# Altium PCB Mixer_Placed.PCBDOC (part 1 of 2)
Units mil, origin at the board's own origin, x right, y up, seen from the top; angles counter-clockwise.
Board outline 16350 x 11350 mil, 2 copper layers (TopLayer, BottomLayer); 554 components, 386 nets, 1551 pads, 0 vias.
Unrouted connection lines stored in the file: 1047.
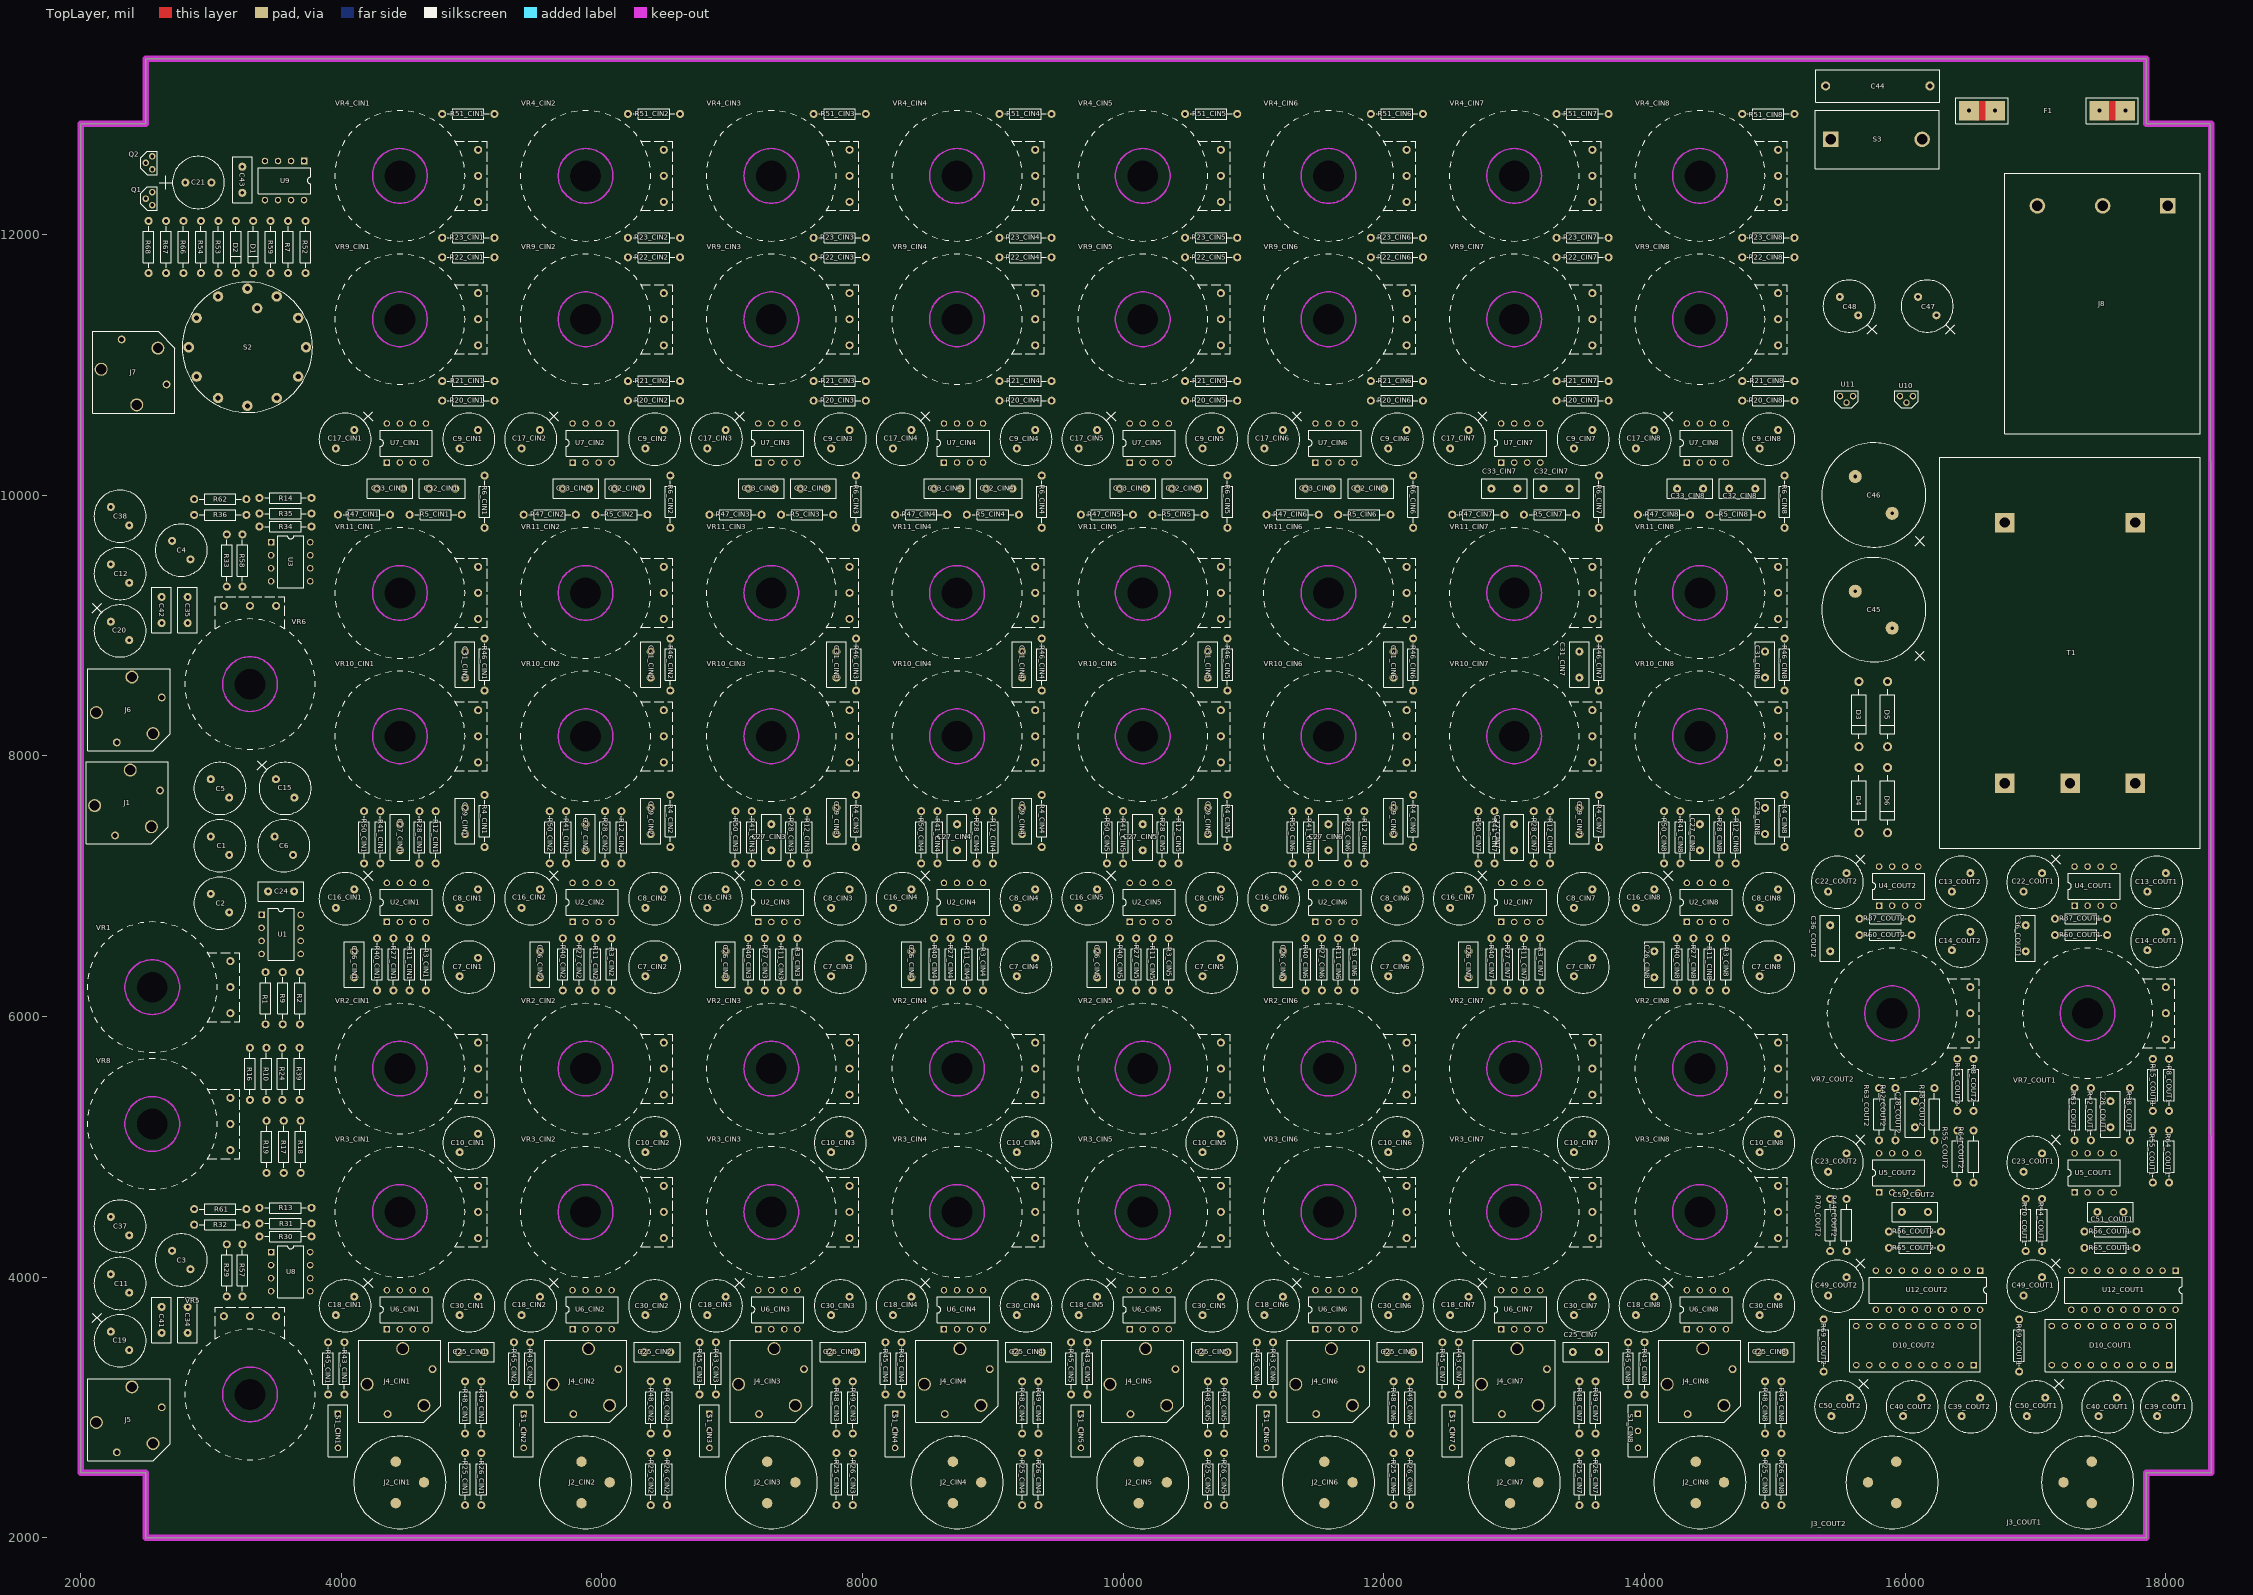
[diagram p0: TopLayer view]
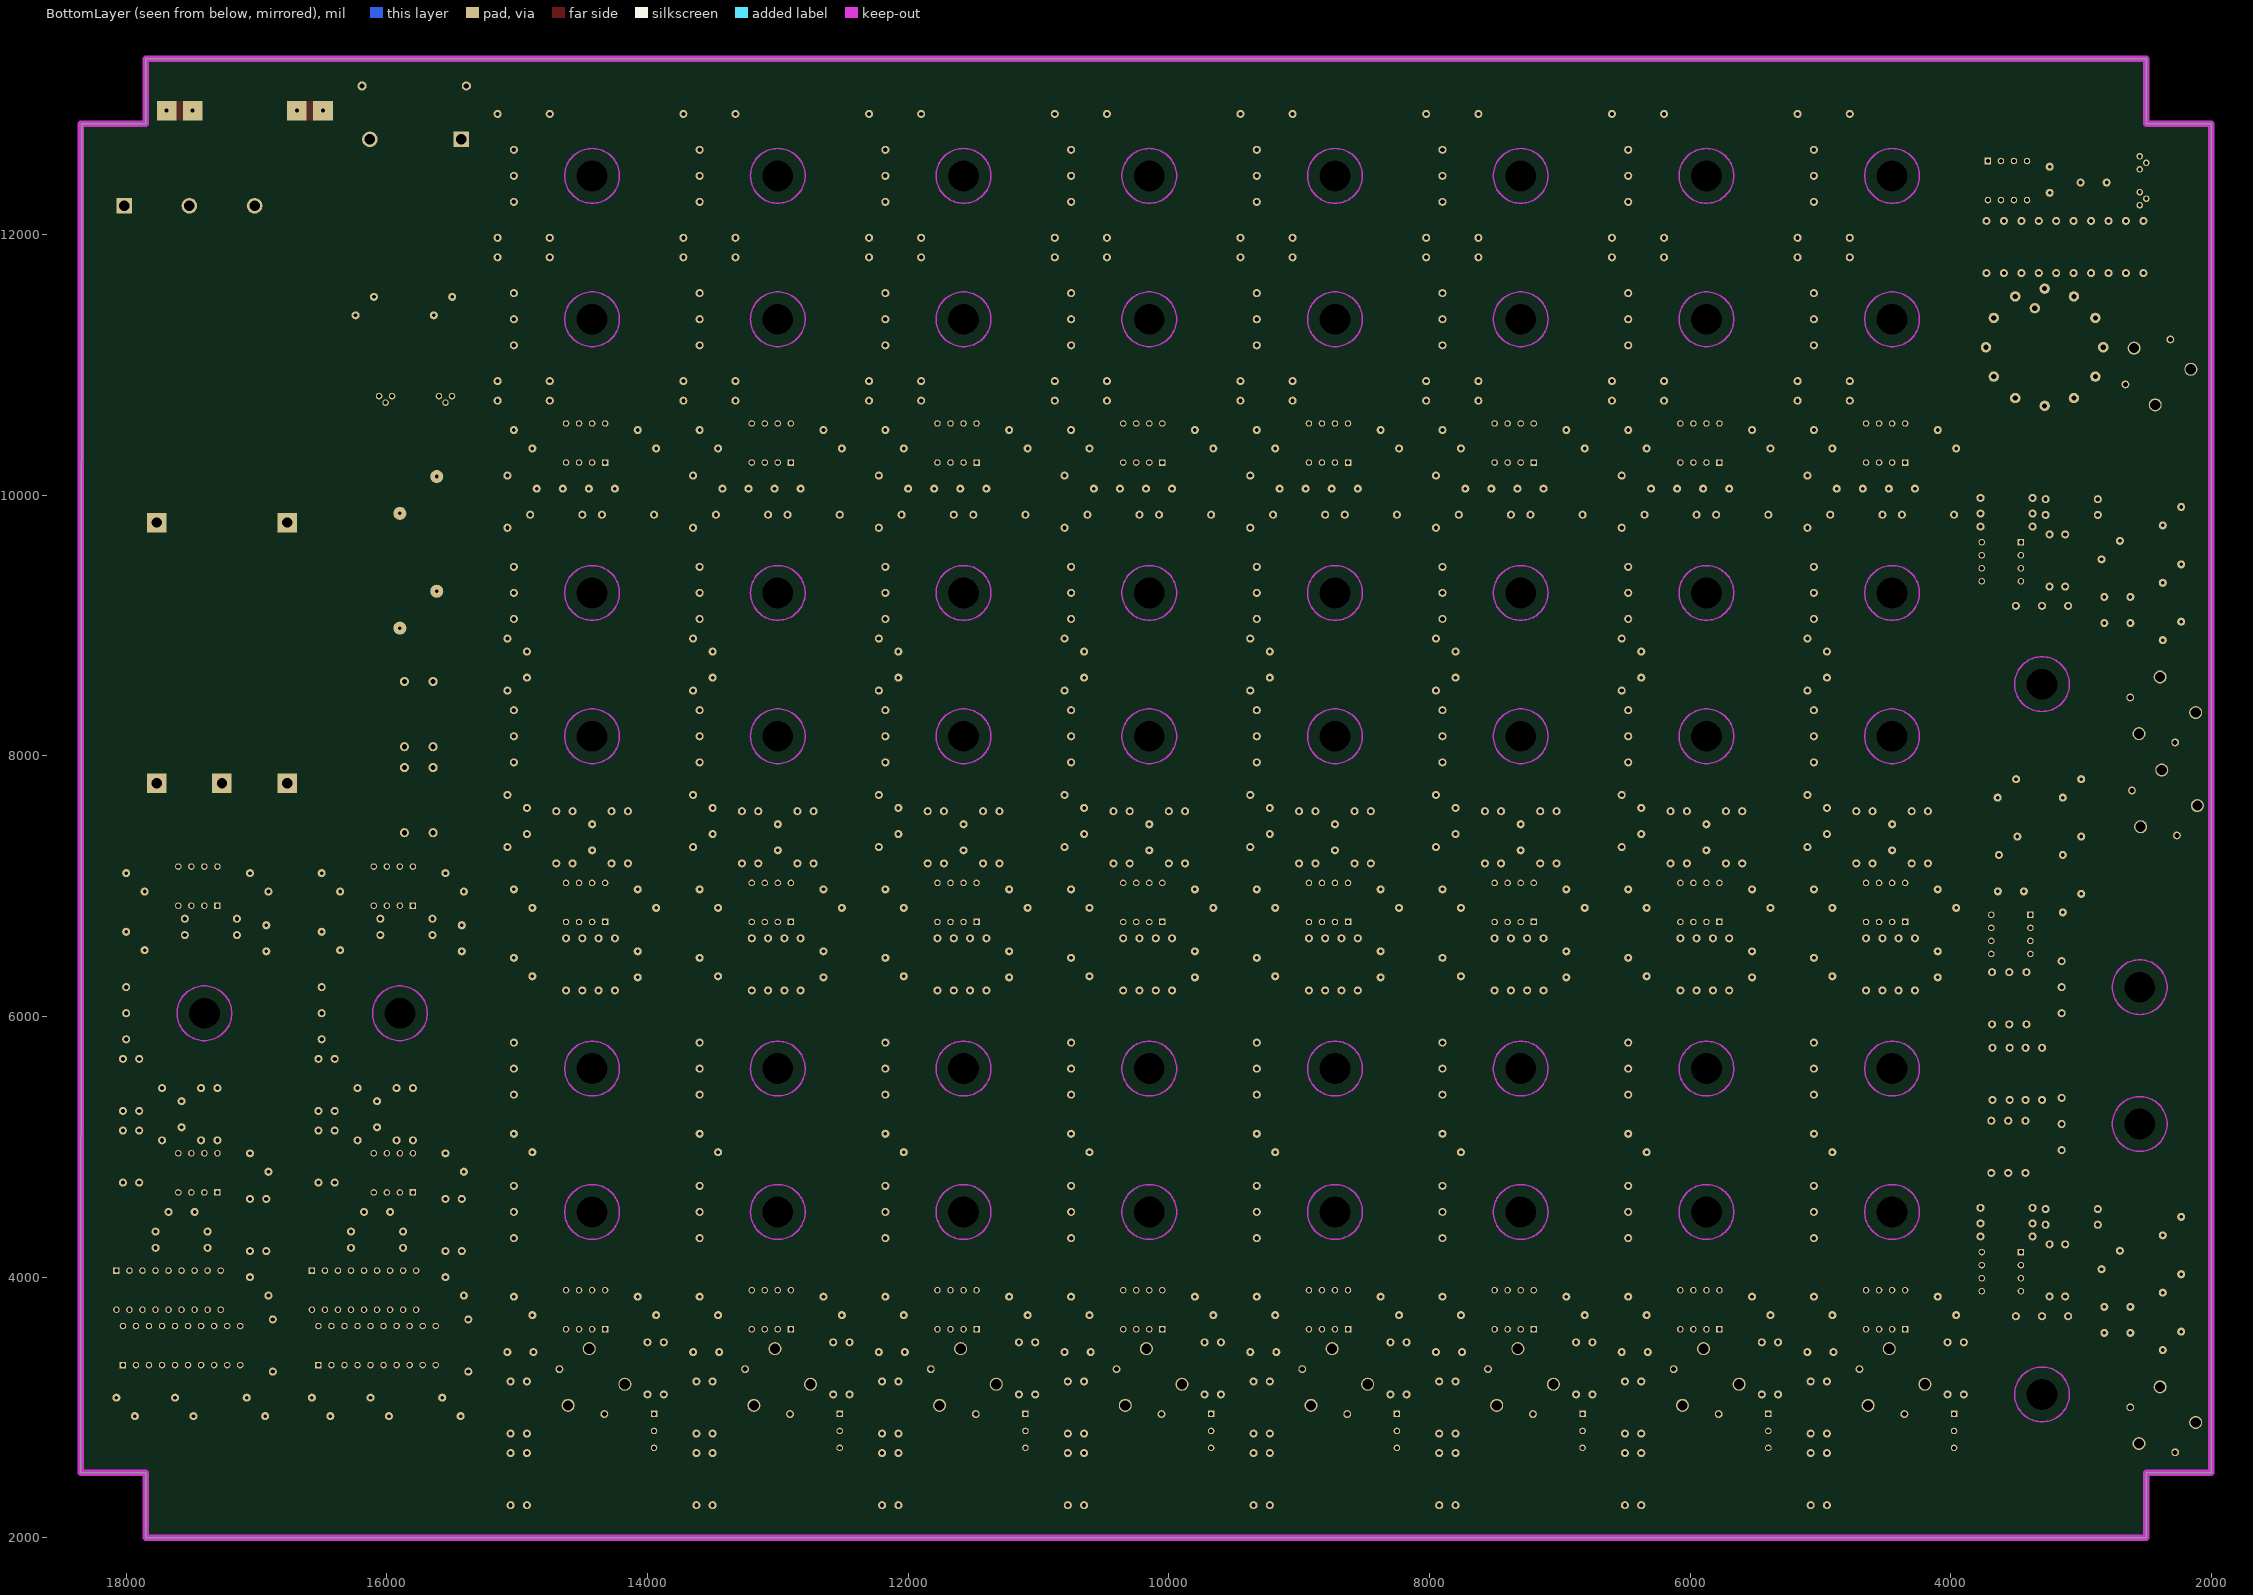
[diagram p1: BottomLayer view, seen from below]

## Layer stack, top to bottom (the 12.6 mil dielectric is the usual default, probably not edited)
TopLayer: signal copper 1.4
Dielectric: core 12.6, FR-4, Dk 4.8
BottomLayer: signal copper 1.4

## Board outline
17850,2500 18350,2500 18340,12850 17850,12850 17850,13350 2500,13350 2500,12850 2000,12850 2000,2500 2500,2500 2500,2000 17850,2000 17850,2500

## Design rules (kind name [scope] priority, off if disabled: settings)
Clearance Clearance_Mains [InNetClass('Mains Voltages') vs Not OnLayer(KeepOutLayer)] p1: gap=100
Clearance [All] p2: gap=10
FabricationTestPointUsage TestPointUsage [All] p1: valid=0 allowmultiple=FALSE
FabricationTestpoint Testpoint [All] p1: side=3 testpointundercomponent=TRUE minsize=40 maxsize=100 preferedsize=60 minholesize=20 maxholesize=40 preferedholesize=32 testpointgrid=1 allowsidetop=TRUE allowsidebottom=TRUE usegrid=TRUE gridtolerance=0.01
PlaneClearance [All] p1: clearance=10
PolygonConnect [All] p1: connectstyle=Relief reliefconductorwidth=10 reliefentries=4 polygonreliefangle="90 Angle"
RoomDefinition CIN7 [InComponentClass('CIN7') vs False] p1: confinementstyle=ConfineIn formatcopy=TRUE lockcomponents=FALSE outline 12350,2050 13775,2050 13775,13300 12350,13300
RoomDefinition CIN6 [InComponentClass('CIN6') vs False] p2: confinementstyle=ConfineIn formatcopy=TRUE lockcomponents=FALSE outline 10925,2050 12350,2050 12350,13300 10925,13300
RoomDefinition CIN5 [InComponentClass('CIN5') vs False] p3: confinementstyle=ConfineIn formatcopy=TRUE lockcomponents=FALSE outline 9500,2050 10925,2050 10925,13300 9500,13300
RoomDefinition CIN4 [InComponentClass('CIN4') vs False] p4: confinementstyle=ConfineIn formatcopy=TRUE lockcomponents=FALSE outline 8075,2050 9500,2050 9500,13300 8075,13300
RoomDefinition CIN3 [InComponentClass('CIN3') vs False] p5: confinementstyle=ConfineIn formatcopy=TRUE lockcomponents=FALSE outline 6650,2050 8075,2050 8075,13300 6650,13300
RoomDefinition CIN2 [InComponentClass('CIN2') vs False] p6: confinementstyle=ConfineIn formatcopy=TRUE lockcomponents=FALSE outline 5225,2050 6650,2050 6650,13300 5225,13300
RoomDefinition CIN1 [InComponentClass('CIN1') vs False] p7: confinementstyle=ConfineIn formatcopy=TRUE lockcomponents=FALSE outline 3800,2050 5225,2050 5225,13300 3800,13300
RoomDefinition COUT2 [InComponentClass('COUT2') vs False] p8: confinementstyle=ConfineIn formatcopy=TRUE lockcomponents=FALSE outline 15250,2050 16750,2050 16750,7260 15250,7260
RoomDefinition CIN8 [InComponentClass('CIN8') vs False] p9: confinementstyle=ConfineIn formatcopy=TRUE lockcomponents=FALSE outline 13775,2050 15200,2050 15200,13300 13775,13300
RoomDefinition Auxilary [InComponentClass('Auxilary') vs False] p10: confinementstyle=ConfineIn formatcopy=TRUE lockcomponents=FALSE outline 2025,4650 3769,4650 3769,7980 2025,7980
RoomDefinition Monitor [InComponentClass('Monitor') vs False] p11: confinementstyle=ConfineIn formatcopy=TRUE lockcomponents=FALSE outline 2000,2550 3791.93,2550 3791.93,4650 2000,4650
RoomDefinition Effects [InComponentClass('Effects') vs False] p12: confinementstyle=ConfineIn formatcopy=TRUE lockcomponents=FALSE outline 2000,8025 3801.93,8025 3801.93,10419 2000,10419
RoomDefinition Headphone [InComponentClass('Headphone') vs False] p13: confinementstyle=ConfineIn formatcopy=TRUE lockcomponents=FALSE outline 2030,10595 3780,10595 3780,12745 2030,12745
RoomDefinition Power [InComponentClass('Power') vs False] p14: confinementstyle=ConfineIn formatcopy=TRUE lockcomponents=FALSE outline 15250,7260 18305,7260 18305,13280 15250,13280
RoomDefinition COUT1 [InComponentClass('COUT1') vs False] p15: confinementstyle=ConfineIn formatcopy=TRUE lockcomponents=FALSE outline 16750,2050 18250,2050 18250,7260 16750,7260
RoutingVias [All] p1: holewidth=28 width=50 viastyle="Through Hole" minholewidth=28 minwidth=50 maxholewidth=28 maxwidth=50
SilkscreenOverComponentPads [All] p1: minsilkscreentomaskgap=10
SolderMaskExpansion SolderMaskExpansion_Vias [IsVia] p1: expansion=-26
SolderMaskExpansion [All] p2: expansion=4
Width Width_Mains [InNetClass('Mains Voltages')] p1: maxlimit=100 minlimit=50 preferedwidth=100
Width [All] p2: maxlimit=20 minlimit=8 preferedwidth=20
24 further rules are at their usual default settings.

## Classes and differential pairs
net class HEADPHONE[1..8]: HEADPHONE1 HEADPHONE2 HEADPHONE3 HEADPHONE4 HEADPHONE5 HEADPHONE6 HEADPHONE7 HEADPHONE8
net class MB[1..2]: MB1 MB2
component class Auxilary: C1 C2 C5 C6 C15 C24 J1 R1 R2 R9 R10 R16 R17 R18 R19 R24 R39 U1 VR1 VR8
component class CIN1: C7_CIN1 C8_CIN1 C9_CIN1 C10_CIN1 C16_CIN1 C17_CIN1 C18_CIN1 C25_CIN1 C26_CIN1 C27_CIN1 C29_CIN1 C30_CIN1 C31_CIN1 C32_CIN1 C33_CIN1 J2_CIN1 J4_CIN1 R3_CIN1 R4_CIN1 R5_CIN1 R6_CIN1 R11_CIN1 R12_CIN1 R20_CIN1 R21_CIN1 R22_CIN1 R23_CIN1 R25_CIN1 R26_CIN1 R27_CIN1 R28_CIN1 R40_CIN1 R41_CIN1 R43_CIN1 R45_CIN1 R46_CIN1 R47_CIN1 R48_CIN1 R49_CIN1 R50_CIN1 R51_CIN1 S1_CIN1 U2_CIN1 U6_CIN1 U7_CIN1 VR2_CIN1 VR3_CIN1 VR4_CIN1 VR9_CIN1 VR10_CIN1 VR11_CIN1
component class CIN2: C7_CIN2 C8_CIN2 C9_CIN2 C10_CIN2 C16_CIN2 C17_CIN2 C18_CIN2 C25_CIN2 C26_CIN2 C27_CIN2 C29_CIN2 C30_CIN2 C31_CIN2 C32_CIN2 C33_CIN2 J2_CIN2 J4_CIN2 R3_CIN2 R4_CIN2 R5_CIN2 R6_CIN2 R11_CIN2 R12_CIN2 R20_CIN2 R21_CIN2 R22_CIN2 R23_CIN2 R25_CIN2 R26_CIN2 R27_CIN2 R28_CIN2 R40_CIN2 R41_CIN2 R43_CIN2 R45_CIN2 R46_CIN2 R47_CIN2 R48_CIN2 R49_CIN2 R50_CIN2 R51_CIN2 S1_CIN2 U2_CIN2 U6_CIN2 U7_CIN2 VR2_CIN2 VR3_CIN2 VR4_CIN2 VR9_CIN2 VR10_CIN2 VR11_CIN2
component class CIN3: C7_CIN3 C8_CIN3 C9_CIN3 C10_CIN3 C16_CIN3 C17_CIN3 C18_CIN3 C25_CIN3 C26_CIN3 C27_CIN3 C29_CIN3 C30_CIN3 C31_CIN3 C32_CIN3 C33_CIN3 J2_CIN3 J4_CIN3 R3_CIN3 R4_CIN3 R5_CIN3 R6_CIN3 R11_CIN3 R12_CIN3 R20_CIN3 R21_CIN3 R22_CIN3 R23_CIN3 R25_CIN3 R26_CIN3 R27_CIN3 R28_CIN3 R40_CIN3 R41_CIN3 R43_CIN3 R45_CIN3 R46_CIN3 R47_CIN3 R48_CIN3 R49_CIN3 R50_CIN3 R51_CIN3 S1_CIN3 U2_CIN3 U6_CIN3 U7_CIN3 VR2_CIN3 VR3_CIN3 VR4_CIN3 VR9_CIN3 VR10_CIN3 VR11_CIN3
component class CIN4: C7_CIN4 C8_CIN4 C9_CIN4 C10_CIN4 C16_CIN4 C17_CIN4 C18_CIN4 C25_CIN4 C26_CIN4 C27_CIN4 C29_CIN4 C30_CIN4 C31_CIN4 C32_CIN4 C33_CIN4 J2_CIN4 J4_CIN4 R3_CIN4 R4_CIN4 R5_CIN4 R6_CIN4 R11_CIN4 R12_CIN4 R20_CIN4 R21_CIN4 R22_CIN4 R23_CIN4 R25_CIN4 R26_CIN4 R27_CIN4 R28_CIN4 R40_CIN4 R41_CIN4 R43_CIN4 R45_CIN4 R46_CIN4 R47_CIN4 R48_CIN4 R49_CIN4 R50_CIN4 R51_CIN4 S1_CIN4 U2_CIN4 U6_CIN4 U7_CIN4 VR2_CIN4 VR3_CIN4 VR4_CIN4 VR9_CIN4 VR10_CIN4 VR11_CIN4
component class CIN5: C7_CIN5 C8_CIN5 C9_CIN5 C10_CIN5 C16_CIN5 C17_CIN5 C18_CIN5 C25_CIN5 C26_CIN5 C27_CIN5 C29_CIN5 C30_CIN5 C31_CIN5 C32_CIN5 C33_CIN5 J2_CIN5 J4_CIN5 R3_CIN5 R4_CIN5 R5_CIN5 R6_CIN5 R11_CIN5 R12_CIN5 R20_CIN5 R21_CIN5 R22_CIN5 R23_CIN5 R25_CIN5 R26_CIN5 R27_CIN5 R28_CIN5 R40_CIN5 R41_CIN5 R43_CIN5 R45_CIN5 R46_CIN5 R47_CIN5 R48_CIN5 R49_CIN5 R50_CIN5 R51_CIN5 S1_CIN5 U2_CIN5 U6_CIN5 U7_CIN5 VR2_CIN5 VR3_CIN5 VR4_CIN5 VR9_CIN5 VR10_CIN5 VR11_CIN5
component class CIN6: C7_CIN6 C8_CIN6 C9_CIN6 C10_CIN6 C16_CIN6 C17_CIN6 C18_CIN6 C25_CIN6 C26_CIN6 C27_CIN6 C29_CIN6 C30_CIN6 C31_CIN6 C32_CIN6 C33_CIN6 J2_CIN6 J4_CIN6 R3_CIN6 R4_CIN6 R5_CIN6 R6_CIN6 R11_CIN6 R12_CIN6 R20_CIN6 R21_CIN6 R22_CIN6 R23_CIN6 R25_CIN6 R26_CIN6 R27_CIN6 R28_CIN6 R40_CIN6 R41_CIN6 R43_CIN6 R45_CIN6 R46_CIN6 R47_CIN6 R48_CIN6 R49_CIN6 R50_CIN6 R51_CIN6 S1_CIN6 U2_CIN6 U6_CIN6 U7_CIN6 VR2_CIN6 VR3_CIN6 VR4_CIN6 VR9_CIN6 VR10_CIN6 VR11_CIN6
component class CIN7: C7_CIN7 C8_CIN7 C9_CIN7 C10_CIN7 C16_CIN7 C17_CIN7 C18_CIN7 C25_CIN7 C26_CIN7 C27_CIN7 C29_CIN7 C30_CIN7 C31_CIN7 C32_CIN7 C33_CIN7 J2_CIN7 J4_CIN7 R3_CIN7 R4_CIN7 R5_CIN7 R6_CIN7 R11_CIN7 R12_CIN7 R20_CIN7 R21_CIN7 R22_CIN7 R23_CIN7 R25_CIN7 R26_CIN7 R27_CIN7 R28_CIN7 R40_CIN7 R41_CIN7 R43_CIN7 R45_CIN7 R46_CIN7 R47_CIN7 R48_CIN7 R49_CIN7 R50_CIN7 R51_CIN7 S1_CIN7 U2_CIN7 U6_CIN7 U7_CIN7 VR2_CIN7 VR3_CIN7 VR4_CIN7 VR9_CIN7 VR10_CIN7 VR11_CIN7
component class CIN8: C7_CIN8 C8_CIN8 C9_CIN8 C10_CIN8 C16_CIN8 C17_CIN8 C18_CIN8 C25_CIN8 C26_CIN8 C27_CIN8 C29_CIN8 C30_CIN8 C31_CIN8 C32_CIN8 C33_CIN8 J2_CIN8 J4_CIN8 R3_CIN8 R4_CIN8 R5_CIN8 R6_CIN8 R11_CIN8 R12_CIN8 R20_CIN8 R21_CIN8 R22_CIN8 R23_CIN8 R25_CIN8 R26_CIN8 R27_CIN8 R28_CIN8 R40_CIN8 R41_CIN8 R43_CIN8 R45_CIN8 R46_CIN8 R47_CIN8 R48_CIN8 R49_CIN8 R50_CIN8 R51_CIN8 S1_CIN8 U2_CIN8 U6_CIN8 U7_CIN8 VR2_CIN8 VR3_CIN8 VR4_CIN8 VR9_CIN8 VR10_CIN8 VR11_CIN8
component class COUT1: C13_COUT1 C14_COUT1 C22_COUT1 C23_COUT1 C28_COUT1 C36_COUT1 C39_COUT1 C40_COUT1 C49_COUT1 C50_COUT1 C51_COUT1 D10_COUT1 J3_COUT1 R8_COUT1 R15_COUT1 R37_COUT1 R38_COUT1 R42_COUT1 R44_COUT1 R55_COUT1 R56_COUT1 R60_COUT1 R63_COUT1 R64_COUT1 R65_COUT1 R69_COUT1 R70_COUT1 U4_COUT1 U5_COUT1 U12_COUT1 VR7_COUT1
component class COUT2: C13_COUT2 C14_COUT2 C22_COUT2 C23_COUT2 C28_COUT2 C36_COUT2 C39_COUT2 C40_COUT2 C49_COUT2 C50_COUT2 C51_COUT2 D10_COUT2 J3_COUT2 R8_COUT2 R15_COUT2 R37_COUT2 R38_COUT2 R42_COUT2 R44_COUT2 R55_COUT2 R56_COUT2 R60_COUT2 R63_COUT2 R64_COUT2 R65_COUT2 R69_COUT2 R70_COUT2 U4_COUT2 U5_COUT2 U12_COUT2 VR7_COUT2
component class Effects: C4 C12 C20 C35 C38 C42 J6 R14 R33 R34 R35 R36 R58 R62 U3 VR6
component class Headphone: C21 C43 D1 D2 J7 Q1 Q2 R7 R52 R53 R54 R59 R66 R67 R68 S2 U9
component class Monitor: C3 C11 C19 C34 C37 C41 J5 R13 R29 R30 R31 R32 R57 R61 U8 VR5
component class Power: C44 C45 C46 C47 C48 D3 D4 D5 D6 F1 J8 S3 T1 U10 U11
channel class "Input channel": CIN1 CIN2 CIN3 CIN4 CIN5 CIN6 CIN7 CIN8
channel class "Output channel": COUT1 COUT2
net class "Mains Voltages": A_FUSE A_IN A_SWITCH NEUTRAL

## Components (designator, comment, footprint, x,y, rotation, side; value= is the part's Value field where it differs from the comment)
C1 "1uF" RB.2/.4-NP 2999,7380.53 r135 top
C2 "1uF" RB.2/.4-NP 2999,6940.4 r135 top
C3 "1uF" RB.2/.4-NP 2701.93,4202.15 r135 top
C4 "1uF" RB.2/.4-NP 2701.93,9649.13 r135 top
C5 "2.2uF" RB.2/.4-NP 2999,7820.66 r135 top
C6 "2.2uF" RB.2/.4-NP 3489,7380.53 r135 top
C7_CIN1 "2.2uF" RB.2/.4-NP 5050,6450 r45 top (schematic designator C7)
C7_CIN2 "2.2uF" RB.2/.4-NP 6475,6450 r45 top (schematic designator C7)
C7_CIN3 "2.2uF" RB.2/.4-NP 7900,6450 r45 top (schematic designator C7)
C7_CIN4 "2.2uF" RB.2/.4-NP 9325,6450 r45 top (schematic designator C7)
C7_CIN5 "2.2uF" RB.2/.4-NP 10750,6450 r45 top (schematic designator C7)
C7_CIN6 "2.2uF" RB.2/.4-NP 12175,6450 r45 top (schematic designator C7)
C7_CIN7 "2.2uF" RB.2/.4-NP 13600,6450 r45 top (schematic designator C7)
C7_CIN8 "2.2uF" RB.2/.4-NP 15025,6450 r45 top (schematic designator C7)
C8_CIN1 "2.2uF" RB.2/.4-NP 5050,6975 r45 top (schematic designator C8)
C8_CIN2 "2.2uF" RB.2/.4-NP 6475,6975 r45 top (schematic designator C8)
C8_CIN3 "2.2uF" RB.2/.4-NP 7900,6975 r45 top (schematic designator C8)
C8_CIN4 "2.2uF" RB.2/.4-NP 9325,6975 r45 top (schematic designator C8)
C8_CIN5 "2.2uF" RB.2/.4-NP 10750,6975 r45 top (schematic designator C8)
C8_CIN6 "2.2uF" RB.2/.4-NP 12175,6975 r45 top (schematic designator C8)
C8_CIN7 "2.2uF" RB.2/.4-NP 13600,6975 r45 top (schematic designator C8)
C8_CIN8 "2.2uF" RB.2/.4-NP 15025,6975 r45 top (schematic designator C8)
C9_CIN1 "2.2uF" RB.2/.4-NP 5050,10500 r45 top (schematic designator C9)
C9_CIN2 "2.2uF" RB.2/.4-NP 6475,10500 r45 top (schematic designator C9)
C9_CIN3 "2.2uF" RB.2/.4-NP 7900,10500 r45 top (schematic designator C9)
C9_CIN4 "2.2uF" RB.2/.4-NP 9325,10500 r45 top (schematic designator C9)
C9_CIN5 "2.2uF" RB.2/.4-NP 10750,10500 r45 top (schematic designator C9)
C9_CIN6 "2.2uF" RB.2/.4-NP 12175,10500 r45 top (schematic designator C9)
C9_CIN7 "2.2uF" RB.2/.4-NP 13600,10500 r45 top (schematic designator C9)
C9_CIN8 "2.2uF" RB.2/.4-NP 15025,10500 r45 top (schematic designator C9)
C10_CIN1 "2.2uF" RB.2/.4-NP 5050,5100 r45 top (schematic designator C10)
C10_CIN2 "2.2uF" RB.2/.4-NP 6475,5100 r45 top (schematic designator C10)
C10_CIN3 "2.2uF" RB.2/.4-NP 7900,5100 r45 top (schematic designator C10)
C10_CIN4 "2.2uF" RB.2/.4-NP 9325,5100 r45 top (schematic designator C10)
C10_CIN5 "2.2uF" RB.2/.4-NP 10750,5100 r45 top (schematic designator C10)
C10_CIN6 "2.2uF" RB.2/.4-NP 12175,5100 r45 top (schematic designator C10)
C10_CIN7 "2.2uF" RB.2/.4-NP 13600,5100 r45 top (schematic designator C10)
C10_CIN8 "2.2uF" RB.2/.4-NP 15025,5100 r45 top (schematic designator C10)
C11 "2.2uF" RB.2/.4-NP 2231.93,4022.15 r135 top
C12 "2.2uF" RB.2/.4-NP 2231.93,9469.13 r135 top
C13_COUT1 "2.2uF" RB.2/.4-NP 18000,7100 r45 top (schematic designator C13)
C13_COUT2 "2.2uF" RB.2/.4-NP 16500,7100 r45 top (schematic designator C13)
C14_COUT1 "2.2uF" RB.2/.4-NP 18000,6650 r45 top (schematic designator C14)
C14_COUT2 "2.2uF" RB.2/.4-NP 16500,6650 r45 top (schematic designator C14)
C15 "10uF" RB.2/.4 3499,7820.66 r135 top
C16_CIN1 "10uF" RB.2/.4 4100,6975 r45 top (schematic designator C16)
C16_CIN2 "10uF" RB.2/.4 5525,6975 r45 top (schematic designator C16)
C16_CIN3 "10uF" RB.2/.4 6950,6975 r45 top (schematic designator C16)
C16_CIN4 "10uF" RB.2/.4 8375,6975 r45 top (schematic designator C16)
C16_CIN5 "10uF" RB.2/.4 9800,6975 r45 top (schematic designator C16)
C16_CIN6 "10uF" RB.2/.4 11225,6975 r45 top (schematic designator C16)
C16_CIN7 "10uF" RB.2/.4 12650,6975 r45 top (schematic designator C16)
C16_CIN8 "10uF" RB.2/.4 14075,6975 r45 top (schematic designator C16)
C17_CIN1 "10uF" RB.2/.4 4100,10500 r45 top (schematic designator C17)
C17_CIN2 "10uF" RB.2/.4 5525,10500 r45 top (schematic designator C17)
C17_CIN3 "10uF" RB.2/.4 6950,10500 r45 top (schematic designator C17)
C17_CIN4 "10uF" RB.2/.4 8375,10500 r45 top (schematic designator C17)
C17_CIN5 "10uF" RB.2/.4 9800,10500 r45 top (schematic designator C17)
C17_CIN6 "10uF" RB.2/.4 11225,10500 r45 top (schematic designator C17)
C17_CIN7 "10uF" RB.2/.4 12650,10500 r45 top (schematic designator C17)
C17_CIN8 "10uF" RB.2/.4 14075,10500 r45 top (schematic designator C17)
C18_CIN1 "10uF" RB.2/.4 4100,3850 r45 top (schematic designator C18)
C18_CIN2 "10uF" RB.2/.4 5525,3850 r45 top (schematic designator C18)
C18_CIN3 "10uF" RB.2/.4 6950,3850 r45 top (schematic designator C18)
C18_CIN4 "10uF" RB.2/.4 8375,3850 r45 top (schematic designator C18)
C18_CIN5 "10uF" RB.2/.4 9800,3850 r45 top (schematic designator C18)
C18_CIN6 "10uF" RB.2/.4 11225,3850 r45 top (schematic designator C18)
C18_CIN7 "10uF" RB.2/.4 12650,3850 r45 top (schematic designator C18)
C18_CIN8 "10uF" RB.2/.4 14075,3850 r45 top (schematic designator C18)
C19 "10uF" RB.2/.4 2231.93,3582.02 r135 top
C20 "10uF" RB.2/.4 2231.93,9029 r135 top
C21 "10uF" RB.2/.4 2804.06,12399 r180 top
C22_COUT1 "10uF" RB.2/.4 17050,7100 r45 top (schematic designator C22)
C22_COUT2 "10uF" RB.2/.4 15550,7100 r45 top (schematic designator C22)
C23_COUT1 "10uF" RB.2/.4 17050,4950 r45 top (schematic designator C23)
C23_COUT2 "10uF" RB.2/.4 15550,4950 r45 top (schematic designator C23)
C24 "270pF" RAD0.2 3639,6960 r180 top
C25_CIN1 "270pF" RAD0.2 4900,3425 r0 top (schematic designator C25)
C25_CIN2 "270pF" RAD0.2 6325,3425 r0 top (schematic designator C25)
C25_CIN3 "270pF" RAD0.2 7750,3425 r0 top (schematic designator C25)
C25_CIN4 "270pF" RAD0.2 9175,3425 r0 top (schematic designator C25)
C25_CIN5 "270pF" RAD0.2 10600,3425 r0 top (schematic designator C25)
C25_CIN6 "270pF" RAD0.2 12025,3425 r0 top (schematic designator C25)
C25_CIN7 "270pF" RAD0.2 13450,3425 r0 top (schematic designator C25)
C25_CIN8 "270pF" RAD0.2 14875,3425 r0 top (schematic designator C25)
C26_CIN1 "270pF" RAD0.2 4100,6300 r90 top (schematic designator C26)
C26_CIN2 "270pF" RAD0.2 5525,6300 r90 top (schematic designator C26)
C26_CIN3 "270pF" RAD0.2 6950,6300 r90 top (schematic designator C26)
C26_CIN4 "270pF" RAD0.2 8375,6300 r90 top (schematic designator C26)
C26_CIN5 "270pF" RAD0.2 9800,6300 r90 top (schematic designator C26)
C26_CIN6 "270pF" RAD0.2 11225,6300 r90 top (schematic designator C26)
C26_CIN7 "270pF" RAD0.2 12650,6300 r90 top (schematic designator C26)
C26_CIN8 "270pF" RAD0.2 14075,6300 r90 top (schematic designator C26)
C27_CIN1 "270pF" RAD0.2 4450,7475 r270 top (schematic designator C27)
C27_CIN2 "270pF" RAD0.2 5875,7475 r270 top (schematic designator C27)
C27_CIN3 "270pF" RAD0.2 7300,7475 r270 top (schematic designator C27)
C27_CIN4 "270pF" RAD0.2 8725,7475 r270 top (schematic designator C27)
C27_CIN5 "270pF" RAD0.2 10150,7475 r270 top (schematic designator C27)
C27_CIN6 "270pF" RAD0.2 11575,7475 r270 top (schematic designator C27)
C27_CIN7 "270pF" RAD0.2 13000,7475 r270 top (schematic designator C27)
C27_CIN8 "270pF" RAD0.2 14425,7475 r270 top (schematic designator C27)
C28_COUT1 "270pF" RAD0.2 17575,5350 r270 top (schematic designator C28)
C28_COUT2 "270pF" RAD0.2 16075,5350 r270 top (schematic designator C28)
C29_CIN1 "100nF" RAD0.2 4950,7400 r90 top (schematic designator C29)
C29_CIN2 "100nF" RAD0.2 6375,7400 r90 top (schematic designator C29)
C29_CIN3 "100nF" RAD0.2 7800,7400 r90 top (schematic designator C29)
C29_CIN4 "100nF" RAD0.2 9225,7400 r90 top (schematic designator C29)
C29_CIN5 "100nF" RAD0.2 10650,7400 r90 top (schematic designator C29)
C29_CIN6 "100nF" RAD0.2 12075,7400 r90 top (schematic designator C29)
C29_CIN7 "100nF" RAD0.2 13500,7400 r90 top (schematic designator C29)
C29_CIN8 "100nF" RAD0.2 14925,7400 r90 top (schematic designator C29)
C30_CIN1 "6.8uF" RB.2/.4-NP 5050,3850 r45 top (schematic designator C30)
C30_CIN2 "6.8uF" RB.2/.4-NP 6475,3850 r45 top (schematic designator C30)
C30_CIN3 "6.8uF" RB.2/.4-NP 7900,3850 r45 top (schematic designator C30)
C30_CIN4 "6.8uF" RB.2/.4-NP 9325,3850 r45 top (schematic designator C30)
C30_CIN5 "6.8uF" RB.2/.4-NP 10750,3850 r45 top (schematic designator C30)
C30_CIN6 "6.8uF" RB.2/.4-NP 12175,3850 r45 top (schematic designator C30)
C30_CIN7 "6.8uF" RB.2/.4-NP 13600,3850 r45 top (schematic designator C30)
C30_CIN8 "6.8uF" RB.2/.4-NP 15025,3850 r45 top (schematic designator C30)
C31_CIN1 "4.7nF" RAD0.2 4950,8600 r90 top (schematic designator C31)
C31_CIN2 "4.7nF" RAD0.2 6375,8600 r90 top (schematic designator C31)
C31_CIN3 "4.7nF" RAD0.2 7800,8600 r90 top (schematic designator C31)
C31_CIN4 "4.7nF" RAD0.2 9225,8600 r90 top (schematic designator C31)
C31_CIN5 "4.7nF" RAD0.2 10650,8600 r90 top (schematic designator C31)
C31_CIN6 "4.7nF" RAD0.2 12075,8600 r90 top (schematic designator C31)
C31_CIN7 "4.7nF" RAD0.2 13500,8600 r90 top (schematic designator C31)
C31_CIN8 "4.7nF" RAD0.2 14925,8600 r90 top (schematic designator C31)
C32_CIN1 "4.7nF" RAD0.2 4875,10050 r180 top (schematic designator C32)
C32_CIN2 "4.7nF" RAD0.2 6300,10050 r180 top (schematic designator C32)
C32_CIN3 "4.7nF" RAD0.2 7725,10050 r180 top (schematic designator C32)
C32_CIN4 "4.7nF" RAD0.2 9150,10050 r180 top (schematic designator C32)
C32_CIN5 "4.7nF" RAD0.2 10575,10050 r180 top (schematic designator C32)
C32_CIN6 "4.7nF" RAD0.2 12000,10050 r180 top (schematic designator C32)
C32_CIN7 "4.7nF" RAD0.2 13425,10050 r180 top (schematic designator C32)
C32_CIN8 "4.7nF" RAD0.2 14850,10050 r180 top (schematic designator C32)
C33_CIN1 "10pF" RAD0.2 4275,10050 r0 top (schematic designator C33)
C33_CIN2 "10pF" RAD0.2 5700,10050 r0 top (schematic designator C33)
C33_CIN3 "10pF" RAD0.2 7125,10050 r0 top (schematic designator C33)
C33_CIN4 "10pF" RAD0.2 8550,10050 r0 top (schematic designator C33)
C33_CIN5 "10pF" RAD0.2 9975,10050 r0 top (schematic designator C33)
C33_CIN6 "10pF" RAD0.2 11400,10050 r0 top (schematic designator C33)
C33_CIN7 "10pF" RAD0.2 12825,10050 r0 top (schematic designator C33)
C33_CIN8 "10pF" RAD0.2 14250,10050 r0 top (schematic designator C33)
C34 "27pF" RAD0.2 2821.93,3772.02 r270 top
C35 "27pF" RAD0.2 2821.93,9219 r270 top
C36_COUT1 "27pF" RAD0.2 16925,6500 r90 top (schematic designator C36)
C36_COUT2 "27pF" RAD0.2 15425,6500 r90 top (schematic designator C36)
C37 "47uF" RB.2/.4-NP 2231.93,4462.28 r135 top
C38 "47uF" RB.2/.4-NP 2231.93,9909.26 r135 top
C39_COUT1 "47uF" RB.2/.4-NP 18075,3075 r45 top (schematic designator C39)
C39_COUT2 "47uF" RB.2/.4-NP 16575,3075 r45 top (schematic designator C39)
C40_COUT1 "47uF" RB.2/.4-NP 17625,3075 r45 top (schematic designator C40)
C40_COUT2 "47uF" RB.2/.4-NP 16125,3075 r45 top (schematic designator C40)
C41 "1nF" RAD0.2 2621.93,3772.02 r270 top
C42 "1nF" RAD0.2 2621.93,9219 r270 top
C43 "22pF" RAD0.2 3241,12520.04 r270 top
C44 "1nF / 2kV" RAD0.8 15390,13140 r0 top
C45 "1000uF" RB.4/.8 15900,8980 r315 top
C46 "1000uF" RB.4/.8 15900,9860 r315 top
C47 "10uF" RB.2/.4 16240,11380 r315 top
C48 "10uF" RB.2/.4 15640,11380 r315 top
C49_COUT1 "10uF" RB.2/.4 17050,4000 r45 top (schematic designator C49)
C49_COUT2 "10uF" RB.2/.4 15550,4000 r45 top (schematic designator C49)
C50_COUT1 "100uF" RB.2/.4 17075,3075 r45 top (schematic designator C50)
C50_COUT2 "100uF" RB.2/.4 15575,3075 r45 top (schematic designator C50)
C51_COUT1 "180pF" RAD0.2 17475,4500 r0 top (schematic designator C51)
C51_COUT2 "180pF" RAD0.2 15975,4500 r0 top (schematic designator C51)
D1 "1N914" DIODE0.4 3324.76,12104.02 r270 top
D2 "1N914" DIODE0.4 3191,12104.02 r270 top
D3 "1N4004" DIODE0.5 15645,8570 r270 top
D4 "1N4004" DIODE0.5 15645,7910 r270 top
D5 "1N4004" DIODE0.5 15865,8570 r270 top
D6 "1N4004" DIODE0.5 15865,7910 r270 top
D10_COUT1 "LED-10 BAR" "LED - 10 BAR HORIZONTAL" 18025,3325 r90 top (schematic designator D10)
D10_COUT2 "LED-10 BAR" "LED - 10 BAR HORIZONTAL" 16525,3325 r90 top (schematic designator D10)
F1 "1A" FUSE 17690,12950 r180 top
J1 "Auxilary In" JACK-6.25MM 2359,7640 r90 top
J2_CIN1 "XLR" XLR-FEMALE 4450,2425 r90 top (schematic designator J2)
J2_CIN2 "XLR" XLR-FEMALE 5875,2425 r90 top (schematic designator J2)
J2_CIN3 "XLR" XLR-FEMALE 7300,2425 r90 top (schematic designator J2)
J2_CIN4 "XLR" XLR-FEMALE 8725,2425 r90 top (schematic designator J2)
J2_CIN5 "XLR" XLR-FEMALE 10150,2425 r90 top (schematic designator J2)
J2_CIN6 "XLR" XLR-FEMALE 11575,2425 r90 top (schematic designator J2)
J2_CIN7 "XLR" XLR-FEMALE 13000,2425 r90 top (schematic designator J2)
J2_CIN8 "XLR" XLR-FEMALE 14425,2425 r90 top (schematic designator J2)
J3_COUT1 "XLR" XLR-MALE 17400,2425 r270 top (schematic designator J3)
J3_COUT2 "XLR" XLR-MALE 15900,2425 r270 top (schematic designator J3)
J4_CIN1 "STEREO JACK" JACK-6.25MM 4450,3200 r90 top (schematic designator J4)
J4_CIN2 "STEREO JACK" JACK-6.25MM 5875,3200 r90 top (schematic designator J4)
J4_CIN3 "STEREO JACK" JACK-6.25MM 7300,3200 r90 top (schematic designator J4)
J4_CIN4 "STEREO JACK" JACK-6.25MM 8725,3200 r90 top (schematic designator J4)
J4_CIN5 "STEREO JACK" JACK-6.25MM 10150,3200 r90 top (schematic designator J4)
J4_CIN6 "STEREO JACK" JACK-6.25MM 11575,3200 r90 top (schematic designator J4)
J4_CIN7 "STEREO JACK" JACK-6.25MM 13000,3200 r90 top (schematic designator J4)
J4_CIN8 "STEREO JACK" JACK-6.25MM 14425,3200 r90 top (schematic designator J4)
J5 "Monitor Send" JACK-6.25MM 2371.93,2907.02 r90 top
J6 "Effects Send" JACK-6.25MM 2371.93,8354 r90 top
J7 "Headphone" JACK-6.25MM 2409.23,10944 r180 top
J8 "CON MAINS" IEC-MAINS 18015,12220 r180 top
Q1 "BC338-25" TO-92A 2550,12325 r270 top
Q2 "BC328-25" TO-92A 2550,12600 r270 top
R1 "22k" AXIAL0.4 3419,6340 r270 top
R2 "22k" AXIAL0.4 3683.45,6340 r270 top
R3_CIN1 "22k" AXIAL0.4 4650,6200 r90 top (schematic designator R3)
R3_CIN2 "22k" AXIAL0.4 6075,6200 r90 top (schematic designator R3)
R3_CIN3 "22k" AXIAL0.4 7500,6200 r90 top (schematic designator R3)
R3_CIN4 "22k" AXIAL0.4 8925,6200 r90 top (schematic designator R3)
R3_CIN5 "22k" AXIAL0.4 10350,6200 r90 top (schematic designator R3)
R3_CIN6 "22k" AXIAL0.4 11775,6200 r90 top (schematic designator R3)
R3_CIN7 "22k" AXIAL0.4 13200,6200 r90 top (schematic designator R3)
R3_CIN8 "22k" AXIAL0.4 14625,6200 r90 top (schematic designator R3)
R4_CIN1 "22k" AXIAL0.4 5100,7300 r90 top (schematic designator R4)
R4_CIN2 "22k" AXIAL0.4 6525,7300 r90 top (schematic designator R4)
R4_CIN3 "22k" AXIAL0.4 7950,7300 r90 top (schematic designator R4)
R4_CIN4 "22k" AXIAL0.4 9375,7300 r90 top (schematic designator R4)
R4_CIN5 "22k" AXIAL0.4 10800,7300 r90 top (schematic designator R4)
R4_CIN6 "22k" AXIAL0.4 12225,7300 r90 top (schematic designator R4)
R4_CIN7 "22k" AXIAL0.4 13650,7300 r90 top (schematic designator R4)
R4_CIN8 "22k" AXIAL0.4 15075,7300 r90 top (schematic designator R4)
R5_CIN1 "22k" AXIAL0.4 4525,9850 r0 top (schematic designator R5)
R5_CIN2 "22k" AXIAL0.4 5950,9850 r0 top (schematic designator R5)
R5_CIN3 "22k" AXIAL0.4 7375,9850 r0 top (schematic designator R5)
R5_CIN4 "22k" AXIAL0.4 8800,9850 r0 top (schematic designator R5)
R5_CIN5 "22k" AXIAL0.4 10225,9850 r0 top (schematic designator R5)
R5_CIN6 "22k" AXIAL0.4 11650,9850 r0 top (schematic designator R5)
R5_CIN7 "22k" AXIAL0.4 13075,9850 r0 top (schematic designator R5)
R5_CIN8 "22k" AXIAL0.4 14500,9850 r0 top (schematic designator R5)
R6_CIN1 "22k" AXIAL0.4 5100,9750 r90 top (schematic designator R6)
R6_CIN2 "22k" AXIAL0.4 6525,9750 r90 top (schematic designator R6)
R6_CIN3 "22k" AXIAL0.4 7950,9750 r90 top (schematic designator R6)
R6_CIN4 "22k" AXIAL0.4 9375,9750 r90 top (schematic designator R6)
R6_CIN5 "22k" AXIAL0.4 10800,9750 r90 top (schematic designator R6)
R6_CIN6 "22k" AXIAL0.4 12225,9750 r90 top (schematic designator R6)
R6_CIN7 "22k" AXIAL0.4 13650,9750 r90 top (schematic designator R6)
R6_CIN8 "22k" AXIAL0.4 15075,9750 r90 top (schematic designator R6)
R7 "22k" AXIAL0.4 3592.26,12104.02 r270 top
R8_COUT1 "22k" AXIAL0.4 18025,5675 r270 top (schematic designator R8)
R8_COUT2 "22k" AXIAL0.4 16525,5675 r270 top (schematic designator R8)
R9 "10R" AXIAL0.4 3551.22,5940 r90 top
R10 "10R" AXIAL0.4 3425.67,5360 r90 top
R11_CIN1 "10R" AXIAL0.4 4525,6200 r90 top (schematic designator R11)
R11_CIN2 "10R" AXIAL0.4 5950,6200 r90 top (schematic designator R11)
R11_CIN3 "10R" AXIAL0.4 7375,6200 r90 top (schematic designator R11)
R11_CIN4 "10R" AXIAL0.4 8800,6200 r90 top (schematic designator R11)
R11_CIN5 "10R" AXIAL0.4 10225,6200 r90 top (schematic designator R11)
R11_CIN6 "10R" AXIAL0.4 11650,6200 r90 top (schematic designator R11)
R11_CIN7 "10R" AXIAL0.4 13075,6200 r90 top (schematic designator R11)
R11_CIN8 "10R" AXIAL0.4 14500,6200 r90 top (schematic designator R11)
R12_CIN1 "10R" AXIAL0.4 4725,7575 r270 top (schematic designator R12)
R12_CIN2 "10R" AXIAL0.4 6150,7575 r270 top (schematic designator R12)
R12_CIN3 "10R" AXIAL0.4 7575,7575 r270 top (schematic designator R12)
R12_CIN4 "10R" AXIAL0.4 9000,7575 r270 top (schematic designator R12)
R12_CIN5 "10R" AXIAL0.4 10425,7575 r270 top (schematic designator R12)
R12_CIN6 "10R" AXIAL0.4 11850,7575 r270 top (schematic designator R12)
R12_CIN7 "10R" AXIAL0.4 13275,7575 r270 top (schematic designator R12)
R12_CIN8 "10R" AXIAL0.4 14700,7575 r270 top (schematic designator R12)
R13 "10R" AXIAL0.4 3771.93,4532.02 r180 top
R14 "10R" AXIAL0.4 3771.93,9979 r180 top
R15_COUT1 "10R" AXIAL0.4 17900,5675 r270 top (schematic designator R15)
R15_COUT2 "10R" AXIAL0.4 16400,5675 r270 top (schematic designator R15)
R16 "15k" AXIAL0.4 3299,5760 r270 top
R17 "15k" AXIAL0.4 3559,5200 r270 top
R18 "15k" AXIAL0.4 3689,4800 r90 top
R19 "15k" AXIAL0.4 3426.78,5200 r270 top
R20_CIN1 "15k" AXIAL0.4 5175,10725 r180 top (schematic designator R20)
R20_CIN2 "15k" AXIAL0.4 6600,10725 r180 top (schematic designator R20)
R20_CIN3 "15k" AXIAL0.4 8025,10725 r180 top (schematic designator R20)
R20_CIN4 "15k" AXIAL0.4 9450,10725 r180 top (schematic designator R20)
R20_CIN5 "15k" AXIAL0.4 10875,10725 r180 top (schematic designator R20)
R20_CIN6 "15k" AXIAL0.4 12300,10725 r180 top (schematic designator R20)
R20_CIN7 "15k" AXIAL0.4 13725,10725 r180 top (schematic designator R20)
R20_CIN8 "15k" AXIAL0.4 15150,10725 r180 top (schematic designator R20)
R21_CIN1 "15k" AXIAL0.4 5175,10875 r180 top (schematic designator R21)
R21_CIN2 "15k" AXIAL0.4 6600,10875 r180 top (schematic designator R21)
R21_CIN3 "15k" AXIAL0.4 8025,10875 r180 top (schematic designator R21)
R21_CIN4 "15k" AXIAL0.4 9450,10875 r180 top (schematic designator R21)
R21_CIN5 "15k" AXIAL0.4 10875,10875 r180 top (schematic designator R21)
R21_CIN6 "15k" AXIAL0.4 12300,10875 r180 top (schematic designator R21)
R21_CIN7 "15k" AXIAL0.4 13725,10875 r180 top (schematic designator R21)
R21_CIN8 "15k" AXIAL0.4 15150,10875 r180 top (schematic designator R21)
R22_CIN1 "15k" AXIAL0.4 5175,11825 r180 top (schematic designator R22)
R22_CIN2 "15k" AXIAL0.4 6600,11825 r180 top (schematic designator R22)
R22_CIN3 "15k" AXIAL0.4 8025,11825 r180 top (schematic designator R22)
R22_CIN4 "15k" AXIAL0.4 9450,11825 r180 top (schematic designator R22)
R22_CIN5 "15k" AXIAL0.4 10875,11825 r180 top (schematic designator R22)
R22_CIN6 "15k" AXIAL0.4 12300,11825 r180 top (schematic designator R22)
R22_CIN7 "15k" AXIAL0.4 13725,11825 r180 top (schematic designator R22)
R22_CIN8 "15k" AXIAL0.4 15150,11825 r180 top (schematic designator R22)
R23_CIN1 "15k" AXIAL0.4 5175,11975 r180 top (schematic designator R23)
R23_CIN2 "15k" AXIAL0.4 6600,11975 r180 top (schematic designator R23)
R23_CIN3 "15k" AXIAL0.4 8025,11975 r180 top (schematic designator R23)
R23_CIN4 "15k" AXIAL0.4 9450,11975 r180 top (schematic designator R23)
R23_CIN5 "15k" AXIAL0.4 10875,11975 r180 top (schematic designator R23)
R23_CIN6 "15k" AXIAL0.4 12300,11975 r180 top (schematic designator R23)
R23_CIN7 "15k" AXIAL0.4 13725,11975 r180 top (schematic designator R23)
R23_CIN8 "15k" AXIAL0.4 15150,11975 r180 top (schematic designator R23)
R24 "2.2k" AXIAL0.4 3547.89,5760 r270 top
R25_CIN1 "2.2k" AXIAL0.4 4950,2250 r90 top (schematic designator R25)
R25_CIN2 "2.2k" AXIAL0.4 6375,2250 r90 top (schematic designator R25)
R25_CIN3 "2.2k" AXIAL0.4 7800,2250 r90 top (schematic designator R25)
R25_CIN4 "2.2k" AXIAL0.4 9225,2250 r90 top (schematic designator R25)
R25_CIN5 "2.2k" AXIAL0.4 10650,2250 r90 top (schematic designator R25)
R25_CIN6 "2.2k" AXIAL0.4 12075,2250 r90 top (schematic designator R25)
R25_CIN7 "2.2k" AXIAL0.4 13500,2250 r90 top (schematic designator R25)
R25_CIN8 "2.2k" AXIAL0.4 14925,2250 r90 top (schematic designator R25)
R26_CIN1 "2.2k" AXIAL0.4 5075,2250 r90 top (schematic designator R26)
R26_CIN2 "2.2k" AXIAL0.4 6500,2250 r90 top (schematic designator R26)
R26_CIN3 "2.2k" AXIAL0.4 7925,2250 r90 top (schematic designator R26)
R26_CIN4 "2.2k" AXIAL0.4 9350,2250 r90 top (schematic designator R26)
R26_CIN5 "2.2k" AXIAL0.4 10775,2250 r90 top (schematic designator R26)
R26_CIN6 "2.2k" AXIAL0.4 12200,2250 r90 top (schematic designator R26)
R26_CIN7 "2.2k" AXIAL0.4 13625,2250 r90 top (schematic designator R26)
R26_CIN8 "2.2k" AXIAL0.4 15050,2250 r90 top (schematic designator R26)
R27_CIN1 "2.2k" AXIAL0.4 4400,6200 r90 top (schematic designator R27)
R27_CIN2 "2.2k" AXIAL0.4 5825,6200 r90 top (schematic designator R27)
R27_CIN3 "2.2k" AXIAL0.4 7250,6200 r90 top (schematic designator R27)
R27_CIN4 "2.2k" AXIAL0.4 8675,6200 r90 top (schematic designator R27)
R27_CIN5 "2.2k" AXIAL0.4 10100,6200 r90 top (schematic designator R27)
R27_CIN6 "2.2k" AXIAL0.4 11525,6200 r90 top (schematic designator R27)
R27_CIN7 "2.2k" AXIAL0.4 12950,6200 r90 top (schematic designator R27)
R27_CIN8 "2.2k" AXIAL0.4 14375,6200 r90 top (schematic designator R27)
R28_CIN1 "2.2k" AXIAL0.4 4600,7175 r90 top (schematic designator R28)
R28_CIN2 "2.2k" AXIAL0.4 6025,7175 r90 top (schematic designator R28)
R28_CIN3 "2.2k" AXIAL0.4 7450,7175 r90 top (schematic designator R28)
R28_CIN4 "2.2k" AXIAL0.4 8875,7175 r90 top (schematic designator R28)
R28_CIN5 "2.2k" AXIAL0.4 10300,7175 r90 top (schematic designator R28)
R28_CIN6 "2.2k" AXIAL0.4 11725,7175 r90 top (schematic designator R28)
R28_CIN7 "2.2k" AXIAL0.4 13150,7175 r90 top (schematic designator R28)
R28_CIN8 "2.2k" AXIAL0.4 14575,7175 r90 top (schematic designator R28)
R29 "2.2k" AXIAL0.4 3121.93,4252.02 r270 top
R30 "2.2k" AXIAL0.4 3371.93,4312.02 r0 top
R31 "2.2k" AXIAL0.4 3771.93,4412.02 r180 top
R32 "2.2k" AXIAL0.4 3271.93,4402.02 r180 top
R33 "2.2k" AXIAL0.4 3121.93,9699 r270 top
R34 "2.2k" AXIAL0.4 3371.93,9759 r0 top
R35 "2.2k" AXIAL0.4 3771.93,9859 r180 top
R36 "2.2k" AXIAL0.4 3271.93,9849 r180 top
R37_COUT1 "2.2k" AXIAL0.4 17150,6750 r0 top (schematic designator R37)
R37_COUT2 "2.2k" AXIAL0.4 15650,6750 r0 top (schematic designator R37)
R38_COUT1 "2.2k" AXIAL0.4 17725,5450 r270 top (schematic designator R38)
R38_COUT2 "2.2k" AXIAL0.4 16225,5450 r270 top (schematic designator R38)
R39 "6.8k" AXIAL0.4 3680.11,5360 r90 top
R40_CIN1 "6.8k" AXIAL0.4 4275,6200 r90 top (schematic designator R40)
R40_CIN2 "6.8k" AXIAL0.4 5700,6200 r90 top (schematic designator R40)
R40_CIN3 "6.8k" AXIAL0.4 7125,6200 r90 top (schematic designator R40)
R40_CIN4 "6.8k" AXIAL0.4 8550,6200 r90 top (schematic designator R40)
R40_CIN5 "6.8k" AXIAL0.4 9975,6200 r90 top (schematic designator R40)
R40_CIN6 "6.8k" AXIAL0.4 11400,6200 r90 top (schematic designator R40)
R40_CIN7 "6.8k" AXIAL0.4 12825,6200 r90 top (schematic designator R40)
R40_CIN8 "6.8k" AXIAL0.4 14250,6200 r90 top (schematic designator R40)
R41_CIN1 "6.8k" AXIAL0.4 4300,7575 r270 top (schematic designator R41)
R41_CIN2 "6.8k" AXIAL0.4 5725,7575 r270 top (schematic designator R41)
R41_CIN3 "6.8k" AXIAL0.4 7150,7575 r270 top (schematic designator R41)
R41_CIN4 "6.8k" AXIAL0.4 8575,7575 r270 top (schematic designator R41)
R41_CIN5 "6.8k" AXIAL0.4 10000,7575 r270 top (schematic designator R41)
R41_CIN6 "6.8k" AXIAL0.4 11425,7575 r270 top (schematic designator R41)
R41_CIN7 "6.8k" AXIAL0.4 12850,7575 r270 top (schematic designator R41)
R41_CIN8 "6.8k" AXIAL0.4 14275,7575 r270 top (schematic designator R41)
R42_COUT1 "6.8k" AXIAL0.4 17425,5050 r90 top (schematic designator R42)
R42_COUT2 "6.8k" AXIAL0.4 15925,5050 r90 top (schematic designator R42)
R43_CIN1 "330R" AXIAL0.4 4025,3500 r270 top (schematic designator R43)
R43_CIN2 "330R" AXIAL0.4 5450,3500 r270 top (schematic designator R43)
R43_CIN3 "330R" AXIAL0.4 6875,3500 r270 top (schematic designator R43)
R43_CIN4 "330R" AXIAL0.4 8300,3500 r270 top (schematic designator R43)
R43_CIN5 "330R" AXIAL0.4 9725,3500 r270 top (schematic designator R43)
R43_CIN6 "330R" AXIAL0.4 11150,3500 r270 top (schematic designator R43)
R43_CIN7 "330R" AXIAL0.4 12575,3500 r270 top (schematic designator R43)
R43_CIN8 "330R" AXIAL0.4 14000,3500 r270 top (schematic designator R43)
R44_COUT1 "330R" AXIAL0.4 17050,4600 r270 top (schematic designator R44)
R44_COUT2 "330R" AXIAL0.4 15550,4600 r270 top (schematic designator R44)
R45_CIN1 "4.7k" AXIAL0.4 3900,3500 r270 top (schematic designator R45)
R45_CIN2 "4.7k" AXIAL0.4 5325,3500 r270 top (schematic designator R45)
R45_CIN3 "4.7k" AXIAL0.4 6750,3500 r270 top (schematic designator R45)
R45_CIN4 "4.7k" AXIAL0.4 8175,3500 r270 top (schematic designator R45)
R45_CIN5 "4.7k" AXIAL0.4 9600,3500 r270 top (schematic designator R45)
R45_CIN6 "4.7k" AXIAL0.4 11025,3500 r270 top (schematic designator R45)
R45_CIN7 "4.7k" AXIAL0.4 12450,3500 r270 top (schematic designator R45)
R45_CIN8 "4.7k" AXIAL0.4 13875,3500 r270 top (schematic designator R45)
R46_CIN1 "4.7k" AXIAL0.4 5100,8900 r270 top (schematic designator R46)
R46_CIN2 "4.7k" AXIAL0.4 6525,8900 r270 top (schematic designator R46)
R46_CIN3 "4.7k" AXIAL0.4 7950,8900 r270 top (schematic designator R46)
R46_CIN4 "4.7k" AXIAL0.4 9375,8900 r270 top (schematic designator R46)
R46_CIN5 "4.7k" AXIAL0.4 10800,8900 r270 top (schematic designator R46)
R46_CIN6 "4.7k" AXIAL0.4 12225,8900 r270 top (schematic designator R46)
R46_CIN7 "4.7k" AXIAL0.4 13650,8900 r270 top (schematic designator R46)
R46_CIN8 "4.7k" AXIAL0.4 15075,8900 r270 top (schematic designator R46)
R47_CIN1 "4.7k" AXIAL0.4 4375,9850 r180 top (schematic designator R47)
R47_CIN2 "4.7k" AXIAL0.4 5800,9850 r180 top (schematic designator R47)
R47_CIN3 "4.7k" AXIAL0.4 7225,9850 r180 top (schematic designator R47)
R47_CIN4 "4.7k" AXIAL0.4 8650,9850 r180 top (schematic designator R47)
R47_CIN5 "4.7k" AXIAL0.4 10075,9850 r180 top (schematic designator R47)
R47_CIN6 "4.7k" AXIAL0.4 11500,9850 r180 top (schematic designator R47)
R47_CIN7 "4.7k" AXIAL0.4 12925,9850 r180 top (schematic designator R47)
R47_CIN8 "4.7k" AXIAL0.4 14350,9850 r180 top (schematic designator R47)
R48_CIN1 "10k" AXIAL0.4 4950,2800 r90 top (schematic designator R48)
R48_CIN2 "10k" AXIAL0.4 6375,2800 r90 top (schematic designator R48)
R48_CIN3 "10k" AXIAL0.4 7800,2800 r90 top (schematic designator R48)
R48_CIN4 "10k" AXIAL0.4 9225,2800 r90 top (schematic designator R48)
R48_CIN5 "10k" AXIAL0.4 10650,2800 r90 top (schematic designator R48)
R48_CIN6 "10k" AXIAL0.4 12075,2800 r90 top (schematic designator R48)
R48_CIN7 "10k" AXIAL0.4 13500,2800 r90 top (schematic designator R48)
R48_CIN8 "10k" AXIAL0.4 14925,2800 r90 top (schematic designator R48)
R49_CIN1 "10k" AXIAL0.4 5075,2800 r90 top (schematic designator R49)
R49_CIN2 "10k" AXIAL0.4 6500,2800 r90 top (schematic designator R49)
R49_CIN3 "10k" AXIAL0.4 7925,2800 r90 top (schematic designator R49)
R49_CIN4 "10k" AXIAL0.4 9350,2800 r90 top (schematic designator R49)
R49_CIN5 "10k" AXIAL0.4 10775,2800 r90 top (schematic designator R49)
R49_CIN6 "10k" AXIAL0.4 12200,2800 r90 top (schematic designator R49)
R49_CIN7 "10k" AXIAL0.4 13625,2800 r90 top (schematic designator R49)
R49_CIN8 "10k" AXIAL0.4 15050,2800 r90 top (schematic designator R49)
R50_CIN1 "10k" AXIAL0.4 4175,7175 r90 top (schematic designator R50)
R50_CIN2 "10k" AXIAL0.4 5600,7175 r90 top (schematic designator R50)
R50_CIN3 "10k" AXIAL0.4 7025,7175 r90 top (schematic designator R50)
R50_CIN4 "10k" AXIAL0.4 8450,7175 r90 top (schematic designator R50)
R50_CIN5 "10k" AXIAL0.4 9875,7175 r90 top (schematic designator R50)
R50_CIN6 "10k" AXIAL0.4 11300,7175 r90 top (schematic designator R50)
R50_CIN7 "10k" AXIAL0.4 12725,7175 r90 top (schematic designator R50)
R50_CIN8 "10k" AXIAL0.4 14150,7175 r90 top (schematic designator R50)
R51_CIN1 "10k" AXIAL0.4 5175,12925 r180 top (schematic designator R51)
R51_CIN2 "10k" AXIAL0.4 6600,12925 r180 top (schematic designator R51)
R51_CIN3 "10k" AXIAL0.4 8025,12925 r180 top (schematic designator R51)
R51_CIN4 "10k" AXIAL0.4 9450,12925 r180 top (schematic designator R51)
R51_CIN5 "10k" AXIAL0.4 10875,12925 r180 top (schematic designator R51)
R51_CIN6 "10k" AXIAL0.4 12300,12925 r180 top (schematic designator R51)
R51_CIN7 "10k" AXIAL0.4 13725,12925 r180 top (schematic designator R51)
R51_CIN8 "10k" AXIAL0.4 15150,12925 r180 top (schematic designator R51)
R52 "10k" AXIAL0.4 3726.02,12104.02 r270 top
R53 "10k" AXIAL0.4 3057.25,12104.02 r270 top
R54 "10k" AXIAL0.4 2923.49,12104.02 r270 top
R55_COUT1 "10k" AXIAL0.4 17900,5125 r270 top (schematic designator R55)
R55_COUT2 "10k" AXIAL0.4 16400,5125 r270 top (schematic designator R55)
R56_COUT1 "10k" AXIAL0.4 17775,4350 r180 top (schematic designator R56)
R56_COUT2 "10k" AXIAL0.4 16275,4350 r180 top (schematic designator R56)
R57 "68k" AXIAL0.4 3241.93,4252.02 r270 top
R58 "68k" AXIAL0.4 3241.93,9699 r270 top
R59 "68k" AXIAL0.4 3458.51,12104.02 r270 top
R60_COUT1 "68k" AXIAL0.4 17550,6625 r180 top (schematic designator R60)
R60_COUT2 "68k" AXIAL0.4 16050,6625 r180 top (schematic designator R60)
R61 "100R" AXIAL0.4 2871.93,4522.02 r0 top
R62 "100R" AXIAL0.4 2871.93,9969 r0 top
R63_COUT1 "100R" AXIAL0.4 17300,5450 r270 top (schematic designator R63)
R63_COUT2 "100R" AXIAL0.4 15800,5450 r270 top (schematic designator R63)
R64_COUT1 "100R" AXIAL0.4 18025,5125 r270 top (schematic designator R64)
R64_COUT2 "100R" AXIAL0.4 16525,5125 r270 top (schematic designator R64)
R65_COUT1 "100R" AXIAL0.4 17375,4225 r0 top (schematic designator R65)
R65_COUT2 "100R" AXIAL0.4 15875,4225 r0 top (schematic designator R65)
R66 "33R" AXIAL0.4 2789.74,12104.02 r270 top
R67 "33R" AXIAL0.4 2655.99,12104.02 r270 top
R68 "68R" AXIAL0.4 2522.23,12104.02 r270 top
R69_COUT1 "270R 1W" AXIAL0.4 16875,3675 r270 top (schematic designator R69)
R69_COUT2 "270R 1W" AXIAL0.4 15375,3675 r270 top (schematic designator R69)
R70_COUT1 "680R" AXIAL0.4 16925,4600 r270 top (schematic designator R70)
R70_COUT2 "680R" AXIAL0.4 15425,4600 r270 top (schematic designator R70)
S1_CIN1 "SW SPDT" SW-SPDT 3975,2950 r270 top (schematic designator S1)
S1_CIN2 "SW SPDT" SW-SPDT 5400,2950 r270 top (schematic designator S1)
S1_CIN3 "SW SPDT" SW-SPDT 6825,2950 r270 top (schematic designator S1)
S1_CIN4 "SW SPDT" SW-SPDT 8250,2950 r270 top (schematic designator S1)
S1_CIN5 "SW SPDT" SW-SPDT 9675,2950 r270 top (schematic designator S1)
S1_CIN6 "SW SPDT" SW-SPDT 11100,2950 r270 top (schematic designator S1)
S1_CIN7 "SW SPDT" SW-SPDT 12525,2950 r270 top (schematic designator S1)
S1_CIN8 "SW SPDT" SW-SPDT 13950,2950 r270 top (schematic designator S1)
S2 "SW-12WAY" SW-12WAY 3280,11135 r180 top
S3 "Power" SW-MAINS 15380,12730 r0 top
T1 "30V CT" TRANSFORMER 16765,9790 r270 top
U1 "LM833M" DIP8 3389,6780 r0 top
U2_CIN1 "LM833M" DIP8 4350,6725 r90 top (schematic designator U2)
U2_CIN2 "LM833M" DIP8 5775,6725 r90 top (schematic designator U2)
U2_CIN3 "LM833M" DIP8 7200,6725 r90 top (schematic designator U2)
U2_CIN4 "LM833M" DIP8 8625,6725 r90 top (schematic designator U2)
U2_CIN5 "LM833M" DIP8 10050,6725 r90 top (schematic designator U2)
U2_CIN6 "LM833M" DIP8 11475,6725 r90 top (schematic designator U2)
U2_CIN7 "LM833M" DIP8 12900,6725 r90 top (schematic designator U2)
U2_CIN8 "LM833M" DIP8 14325,6725 r90 top (schematic designator U2)
U3 "LM833M" DIP8 3461.93,9639 r0 top
U4_COUT1 "LM833M" DIP8 17300,6850 r90 top (schematic designator U4)
U4_COUT2 "LM833M" DIP8 15800,6850 r90 top (schematic designator U4)
U5_COUT1 "LM833M" DIP8 17300,4650 r90 top (schematic designator U5)
U5_COUT2 "LM833M" DIP8 15800,4650 r90 top (schematic designator U5)
U6_CIN1 "SSM2017P (8)" DIP8 4350,3600 r90 top (schematic designator U6)
U6_CIN2 "SSM2017P (8)" DIP8 5775,3600 r90 top (schematic designator U6)
U6_CIN3 "SSM2017P (8)" DIP8 7200,3600 r90 top (schematic designator U6)
U6_CIN4 "SSM2017P (8)" DIP8 8625,3600 r90 top (schematic designator U6)
U6_CIN5 "SSM2017P (8)" DIP8 10050,3600 r90 top (schematic designator U6)
U6_CIN6 "SSM2017P (8)" DIP8 11475,3600 r90 top (schematic designator U6)
U6_CIN7 "SSM2017P (8)" DIP8 12900,3600 r90 top (schematic designator U6)
U6_CIN8 "SSM2017P (8)" DIP8 14325,3600 r90 top (schematic designator U6)
U7_CIN1 "OP27C" DIP8 4350,10250 r90 top (schematic designator U7)
U7_CIN2 "OP27C" DIP8 5775,10250 r90 top (schematic designator U7)
U7_CIN3 "OP27C" DIP8 7200,10250 r90 top (schematic designator U7)
U7_CIN4 "OP27C" DIP8 8625,10250 r90 top (schematic designator U7)
U7_CIN5 "OP27C" DIP8 10050,10250 r90 top (schematic designator U7)
U7_CIN6 "OP27C" DIP8 11475,10250 r90 top (schematic designator U7)
U7_CIN7 "OP27C" DIP8 12900,10250 r90 top (schematic designator U7)
U7_CIN8 "OP27C" DIP8 14325,10250 r90 top (schematic designator U7)
U8 "LM833M" DIP8 3461.93,4192.02 r0 top
U9 "TL071" DIP8 3715,12564.04 r270 top
U10 "78L15" TO-92A 15960,10760 r0 top
U11 "79L15" TO-92A 15500,10760 r0 top
U12_COUT1 "LM3915N(18)" DIP18 18075,4050 r270 top (schematic designator U12)
U12_COUT2 "LM3915N(18)" DIP18 16575,4050 r270 top (schematic designator U12)
VR1 "10k LOG" "POT - 24MM" 2550,6225 r90 top
VR2_CIN1 "10k LOG" "POT - 24MM" 4450,5600 r90 top (schematic designator VR2)
VR2_CIN2 "10k LOG" "POT - 24MM" 5875,5600 r90 top (schematic designator VR2)
VR2_CIN3 "10k LOG" "POT - 24MM" 7300,5600 r90 top (schematic designator VR2)
VR2_CIN4 "10k LOG" "POT - 24MM" 8725,5600 r90 top (schematic designator VR2)
VR2_CIN5 "10k LOG" "POT - 24MM" 10150,5600 r90 top (schematic designator VR2)
VR2_CIN6 "10k LOG" "POT - 24MM" 11575,5600 r90 top (schematic designator VR2)
VR2_CIN7 "10k LOG" "POT - 24MM" 13000,5600 r90 top (schematic designator VR2)
VR2_CIN8 "10k LOG" "POT - 24MM" 14425,5600 r90 top (schematic designator VR2)
VR3_CIN1 "10k LOG" "POT - 24MM" 4450,4500 r90 top (schematic designator VR3)
VR3_CIN2 "10k LOG" "POT - 24MM" 5875,4500 r90 top (schematic designator VR3)
VR3_CIN3 "10k LOG" "POT - 24MM" 7300,4500 r90 top (schematic designator VR3)
VR3_CIN4 "10k LOG" "POT - 24MM" 8725,4500 r90 top (schematic designator VR3)
VR3_CIN5 "10k LOG" "POT - 24MM" 10150,4500 r90 top (schematic designator VR3)
VR3_CIN6 "10k LOG" "POT - 24MM" 11575,4500 r90 top (schematic designator VR3)
VR3_CIN7 "10k LOG" "POT - 24MM" 13000,4500 r90 top (schematic designator VR3)
VR3_CIN8 "10k LOG" "POT - 24MM" 14425,4500 r90 top (schematic designator VR3)
VR4_CIN1 "10K LOG" "POT - 24MM" 4450,12450 r90 top (schematic designator VR4)
VR4_CIN2 "10K LOG" "POT - 24MM" 5875,12450 r90 top (schematic designator VR4)
VR4_CIN3 "10K LOG" "POT - 24MM" 7300,12450 r90 top (schematic designator VR4)
VR4_CIN4 "10K LOG" "POT - 24MM" 8725,12450 r90 top (schematic designator VR4)
VR4_CIN5 "10K LOG" "POT - 24MM" 10150,12450 r90 top (schematic designator VR4)
VR4_CIN6 "10K LOG" "POT - 24MM" 11575,12450 r90 top (schematic designator VR4)
VR4_CIN7 "10K LOG" "POT - 24MM" 13000,12450 r90 top (schematic designator VR4)
VR4_CIN8 "10K LOG" "POT - 24MM" 14425,12450 r90 top (schematic designator VR4)
VR5 "10k LOG" "POT - 24MM" 3300,3100 r180 top
VR6 "10k LOG" "POT - 24MM" 3300,8550 r180 top
VR7_COUT1 "10k LOG" "POT - 24MM" 17400,6025 r90 top (schematic designator VR7)
VR7_COUT2 "10k LOG" "POT - 24MM" 15900,6025 r90 top (schematic designator VR7)
VR8 "10K LIN" "POT - 24MM" 2550,5175 r90 top
VR9_CIN1 "10K LIN" "POT - 24MM" 4450,11350 r90 top (schematic designator VR9)
VR9_CIN2 "10K LIN" "POT - 24MM" 5875,11350 r90 top (schematic designator VR9)
VR9_CIN3 "10K LIN" "POT - 24MM" 7300,11350 r90 top (schematic designator VR9)
VR9_CIN4 "10K LIN" "POT - 24MM" 8725,11350 r90 top (schematic designator VR9)
VR9_CIN5 "10K LIN" "POT - 24MM" 10150,11350 r90 top (schematic designator VR9)
VR9_CIN6 "10K LIN" "POT - 24MM" 11575,11350 r90 top (schematic designator VR9)
VR9_CIN7 "10K LIN" "POT - 24MM" 13000,11350 r90 top (schematic designator VR9)
VR9_CIN8 "10K LIN" "POT - 24MM" 14425,11350 r90 top (schematic designator VR9)
VR10_CIN1 "100K LIN" "POT - 24MM" 4450,8150 r90 top (schematic designator VR10)
VR10_CIN2 "100K LIN" "POT - 24MM" 5875,8150 r90 top (schematic designator VR10)
VR10_CIN3 "100K LIN" "POT - 24MM" 7300,8150 r90 top (schematic designator VR10)
VR10_CIN4 "100K LIN" "POT - 24MM" 8725,8150 r90 top (schematic designator VR10)
VR10_CIN5 "100K LIN" "POT - 24MM" 10150,8150 r90 top (schematic designator VR10)
VR10_CIN6 "100K LIN" "POT - 24MM" 11575,8150 r90 top (schematic designator VR10)
VR10_CIN7 "100K LIN" "POT - 24MM" 13000,8150 r90 top (schematic designator VR10)
VR10_CIN8 "100K LIN" "POT - 24MM" 14425,8150 r90 top (schematic designator VR10)
VR11_CIN1 "20K LIN" "POT - 24MM" 4450,9250 r90 top (schematic designator VR11)
VR11_CIN2 "20K LIN" "POT - 24MM" 5875,9250 r90 top (schematic designator VR11)
VR11_CIN3 "20K LIN" "POT - 24MM" 7300,9250 r90 top (schematic designator VR11)
VR11_CIN4 "20K LIN" "POT - 24MM" 8725,9250 r90 top (schematic designator VR11)
VR11_CIN5 "20K LIN" "POT - 24MM" 10150,9250 r90 top (schematic designator VR11)
VR11_CIN6 "20K LIN" "POT - 24MM" 11575,9250 r90 top (schematic designator VR11)
VR11_CIN7 "20K LIN" "POT - 24MM" 13000,9250 r90 top (schematic designator VR11)
VR11_CIN8 "20K LIN" "POT - 24MM" 14425,9250 r90 top (schematic designator VR11)

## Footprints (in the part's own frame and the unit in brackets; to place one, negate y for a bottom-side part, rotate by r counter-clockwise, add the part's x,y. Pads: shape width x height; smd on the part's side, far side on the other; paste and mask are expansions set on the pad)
AXIAL0.4 [mil]
  round 62 hole 32: 1(0,0) 2(400,0)
  silkscreen extent 40,-40 360,40
DIODE0.4 [mil]
  round 62 hole 32: 1(0,0) 2(400,0)
  silkscreen extent 40,-40 360,40
DIODE0.5 [mil]
  round 70 hole 40: 1(0,0) 2(500,0)
  silkscreen extent 60,-55 440,55
DIP8 [mil]
  rect 50x50 hole 32: 1(0,0)
  round 50 hole 32: 2(0,-100) 3(0,-200) 4(0,-300) 5(300,-300) 6(300,-200) 7(300,-100) 8(300,0)
  silkscreen extent 50,-350 250,50
DIP18 [mil]
  rect 50x50 hole 32: 1(0,0)
  round 50 hole 32: 2(0,-100) 3(0,-200) 4(0,-300) 5(0,-400) 6(0,-500) 7(0,-600) 8(0,-700) 9(0,-800) 10(300,-800) 11(300,-700) 12(300,-600) 13(300,-500) 14(300,-400) 15(300,-300) 16(300,-200) 17(300,-100) 18(300,0)
  silkscreen extent 50,-850 250,50
FUSE [mil]
  rect 150x150 hole 30: 1(0,0) 1(200,0) 2(1000,0) 2(1200,0)
  TopLayer region: 1150,75 1050,75 1050,-75 1150,-75
  TopLayer region: 150,75 50,75 50,-75 150,-75
  silkscreen extent -100,-100 1300,100
IEC-MAINS [mil]
  rect 120x120 hole 80: 1(0,0)
  round 120 hole 80: 2(500,0) 3(1000,0)
  silkscreen extent -250,-250 1250,1750
JACK-6.25MM [mil]
  round 60 hole 39: 0(-251,94) 0(94,-251)
  round 100 hole 78: 1(251,-22) 2(-22,251) 3(-184,-184)
  silkscreen extent -315,-315 315,315
"LED - 10 BAR HORIZONTAL" [mil]
  rect 50x50 hole 32: 1(0,0)
  round 50 hole 32: 2(300,0) 3(0,100) 4(300,100) 5(0,200) 6(300,200) 7(0,300) 8(300,300) 9(0,400) 10(300,400) 11(0,500) 12(300,500) 13(0,600) 14(300,600) 15(0,700) 16(300,700) 17(0,800) 18(300,800) 19(0,900) 20(300,900)
  silkscreen extent -50,-50 350,950
"POT - 24MM" [mil]
  round 62 hole 35: 1(-200,-600) 2(0,-600) 3(200,-600)
  round 50 hole 236.22 unplated: MNT(0,0)
  KeepOutLayer circle w10: c0,0 r210
  silkscreen extent -500,-670 500,500
RAD0.2 [mil]
  round 62 hole 28: 1(0,0) 2(200,0)
  silkscreen extent -75,-75 275,75
RAD0.8 [mil]
  round 70 hole 40: 1(0,0) 2(800,0)
  silkscreen extent -75,-125 875,125
RB.2/.4 [mil]
  round 62 hole 28: 1(0,0) 2(-200,0)
  silkscreen extent -300,-200 200,200
RB.2/.4-NP [mil]
  round 62 hole 28: 1(0,0) 2(-200,0)
  silkscreen extent -300,-200 100,200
